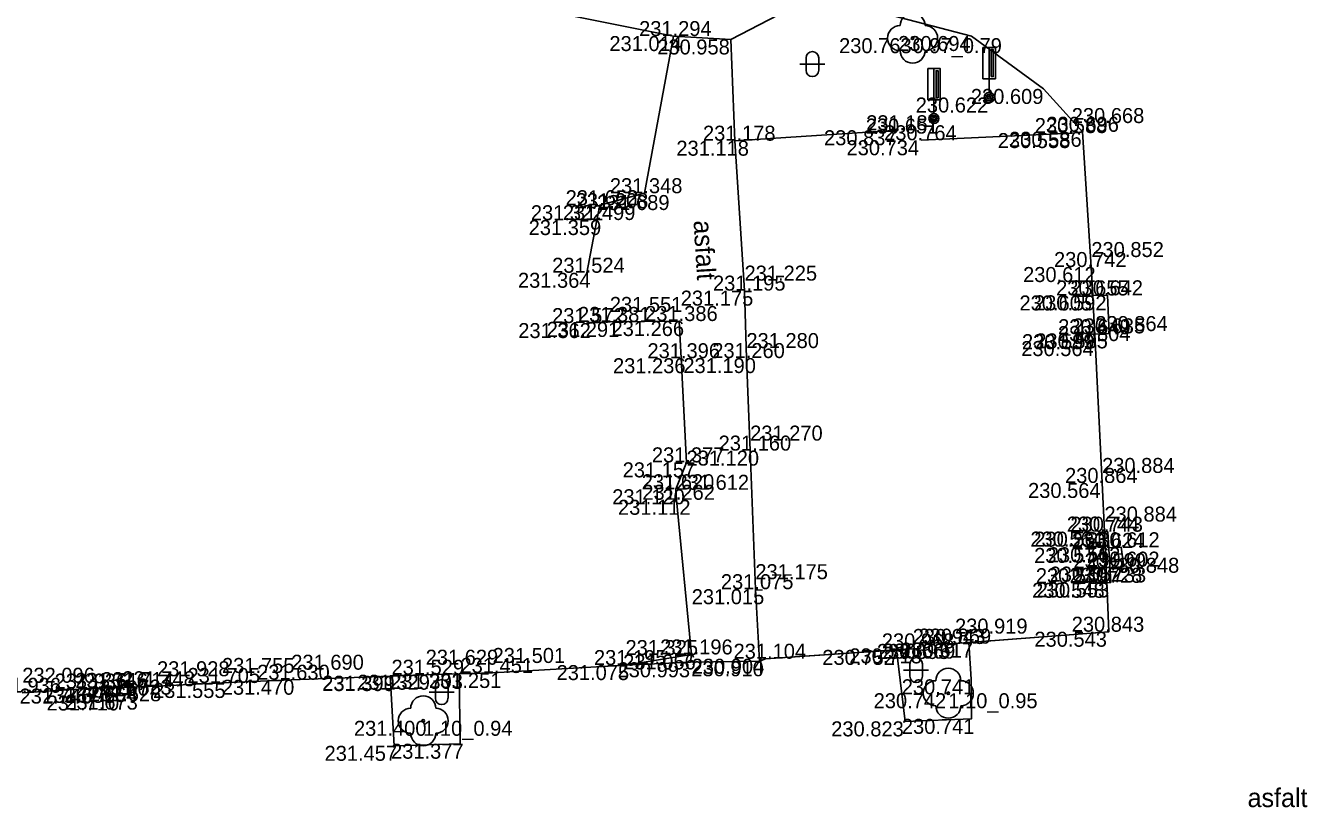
# Model space of a CAD drawing. Extents: x -599516 to -599132, y -1163668 to -1163119.
# Drawn here: x -599461.53 to -599435.91, y -1163173.88 to -1163158.24 of the extents above; entities that cross this region are included whole.
import ezdxf

# ---------------------------------------------------------------- set-up
doc = ezdxf.new("R2010")
doc.units = 0
for name, color, linetype in [('Bod-oznac1', 7, 'Continuous'), ('Bod-oznac2', 7, 'Continuous'), ('Bod-oznac3', 7, 'Continuous'), ('Bod-vyska1', 7, 'Continuous'), ('Bod-vyska2', 7, 'Continuous'), ('Bod-vyska3', 7, 'Continuous'), ('Z_cela-hrobu-dolni-linie', 7, 'Continuous'), ('Z_cela-hrobu-horni-linie', 7, 'Continuous'), ('Z_chodnik', 7, 'Continuous'), ('Z_komunikace', 7, 'Continuous'), ('Z_kultury-znacky', 7, 'Continuous'), ('Z_obvod-kmene-spodek-ve-vysce1_2m', 7, 'Continuous'), ('Z_popis-budov-povrchu', 7, 'Continuous'), ('Z_stromy-kere', 7, 'Continuous'), ('Z_znacky-ostatni-orientacni-sloupek', 7, 'Continuous'), ('Z_zpevnene-plochy', 7, 'Continuous')]:
    doc.layers.add(name, color=color, linetype=linetype)

msp = doc.modelspace()

# ---------------------------------------------------------------- linework, layer by layer
at = {"layer": 'Bod-oznac1'}
for p, q in [((-599448.581, -1163158.452), (-599448.581, -1163158.452)), ((-599443.802, -1163158.494), (-599443.802, -1163158.494)), ((-599442.623, -1163158.451), (-599442.623, -1163158.451)), ((-599447.439, -1163158.52), (-599447.439, -1163158.52)), ((-599441.182, -1163159.51), (-599441.182, -1163159.51)), ((-599442.272, -1163159.681), (-599442.272, -1163159.681)), ((-599443.375, -1163160.103), (-599443.375, -1163160.103)), ((-599447.355, -1163160.545), (-599447.355, -1163160.545)), ((-599444.092, -1163160.336), (-599444.092, -1163160.336)), ((-599443.63, -1163160.536), (-599443.63, -1163160.536)), ((-599440.62, -1163160.392), (-599440.62, -1163160.392)), ((-599440.405, -1163160.367), (-599440.405, -1163160.367)), ((-599450.056, -1163161.836), (-599450.056, -1163161.836)), ((-599449.16, -1163161.595), (-599449.16, -1163161.595)), ((-599450.112, -1163162.132), (-599450.112, -1163162.132)), ((-599440.229, -1163163.072), (-599440.229, -1163163.072)), ((-599450.314, -1163163.187), (-599450.314, -1163163.187)), ((-599447.162, -1163163.544), (-599447.162, -1163163.544)), ((-599439.907, -1163163.638), (-599439.907, -1163163.638)), ((-599440.199, -1163163.641), (-599440.199, -1163163.641)), ((-599448.466, -1163164.152), (-599448.466, -1163164.152)), ((-599450.32, -1163164.193), (-599450.32, -1163164.193)), ((-599449.855, -1163164.17), (-599449.855, -1163164.17)), ((-599439.87, -1163164.399), (-599439.87, -1163164.399)), ((-599440.158, -1163164.415), (-599440.158, -1163164.415)), ((-599440.151, -1163164.553), (-599440.151, -1163164.553)), ((-599448.426, -1163164.896), (-599448.426, -1163164.896)), ((-599447.125, -1163164.893), (-599447.125, -1163164.893)), ((-599447.05, -1163166.744), (-599447.05, -1163166.744)), ((-599448.323, -1163166.979), (-599448.323, -1163166.979)), ((-599440.014, -1163167.391), (-599440.014, -1163167.391)), ((-599448.535, -1163167.517), (-599448.535, -1163167.517)), ((-599448.522, -1163167.728), (-599448.522, -1163167.728)), ((-599439.967, -1163168.364), (-599439.967, -1163168.364)), ((-599439.901, -1163168.366), (-599439.901, -1163168.366)), ((-599439.879, -1163168.691), (-599439.879, -1163168.691)), ((-599439.631, -1163168.678), (-599439.631, -1163168.678)), ((-599439.858, -1163169.096), (-599439.858, -1163169.096)), ((-599439.582, -1163169.065), (-599439.582, -1163169.065)), ((-599446.946, -1163169.516), (-599446.946, -1163169.516)), ((-599439.921, -1163169.388), (-599439.921, -1163169.388)), ((-599439.842, -1163169.381), (-599439.842, -1163169.381)), ((-599439.876, -1163170.367), (-599439.876, -1163170.367)), ((-599444.126, -1163170.73), (-599444.126, -1163170.73)), ((-599443.689, -1163170.7), (-599443.689, -1163170.7)), ((-599443.059, -1163170.612), (-599443.059, -1163170.612)), ((-599442.954, -1163170.605), (-599442.954, -1163170.605)), ((-599442.678, -1163170.584), (-599442.678, -1163170.584)), ((-599449.542, -1163171.034), (-599449.542, -1163171.034)), ((-599448.244, -1163170.978), (-599448.244, -1163170.978)), ((-599448.224, -1163170.821), (-599448.224, -1163170.821)), ((-599446.865, -1163170.958), (-599446.865, -1163170.958)), ((-599446.74, -1163170.907), (-599446.74, -1163170.907)), ((-599456.224, -1163171.327), (-599456.224, -1163171.327)), ((-599454.25, -1163171.247), (-599454.25, -1163171.247)), ((-599454.25, -1163171.254), (-599454.25, -1163171.254)), ((-599453.537, -1163171.227), (-599453.537, -1163171.227)), ((-599452.868, -1163171.21), (-599452.868, -1163171.21)), ((-599452.199, -1163171.192), (-599452.199, -1163171.192)), ((-599442.63, -1163171.319), (-599442.63, -1163171.319)), ((-599460.278, -1163171.504), (-599460.278, -1163171.504)), ((-599459.853, -1163171.491), (-599459.853, -1163171.491)), ((-599459.384, -1163171.475), (-599459.384, -1163171.475)), ((-599458.908, -1163171.458), (-599458.908, -1163171.458)), ((-599457.61, -1163171.392), (-599457.61, -1163171.392)), ((-599459.842, -1163171.642), (-599459.842, -1163171.642)), ((-599459.375, -1163171.625), (-599459.375, -1163171.625)), ((-599443.088, -1163171.597), (-599443.088, -1163171.597)), ((-599453.586, -1163172.149), (-599453.586, -1163172.149)), ((-599443.949, -1163172.16), (-599443.949, -1163172.16)), ((-599442.627, -1163172.11), (-599442.627, -1163172.11)), ((-599452.848, -1163172.607), (-599452.848, -1163172.607)), ((-599454.168, -1163172.649), (-599454.168, -1163172.649))]:
    msp.add_line(p, q, dxfattribs=at)
at = {"layer": 'Bod-oznac2'}
for p, q in [((-599448.581, -1163158.452), (-599448.581, -1163158.452)), ((-599447.355, -1163160.545), (-599447.355, -1163160.545)), ((-599444.092, -1163160.336), (-599444.092, -1163160.336)), ((-599443.63, -1163160.536), (-599443.63, -1163160.536)), ((-599440.62, -1163160.392), (-599440.62, -1163160.392)), ((-599440.405, -1163160.367), (-599440.405, -1163160.367)), ((-599450.056, -1163161.836), (-599450.056, -1163161.836)), ((-599449.16, -1163161.595), (-599449.16, -1163161.595)), ((-599450.112, -1163162.132), (-599450.112, -1163162.132)), ((-599440.229, -1163163.072), (-599440.229, -1163163.072)), ((-599450.314, -1163163.187), (-599450.314, -1163163.187)), ((-599447.162, -1163163.544), (-599447.162, -1163163.544)), ((-599439.907, -1163163.638), (-599439.907, -1163163.638)), ((-599440.199, -1163163.641), (-599440.199, -1163163.641)), ((-599448.466, -1163164.152), (-599448.466, -1163164.152)), ((-599450.32, -1163164.193), (-599450.32, -1163164.193)), ((-599449.855, -1163164.17), (-599449.855, -1163164.17)), ((-599439.87, -1163164.399), (-599439.87, -1163164.399)), ((-599440.158, -1163164.415), (-599440.158, -1163164.415)), ((-599440.151, -1163164.553), (-599440.151, -1163164.553)), ((-599448.426, -1163164.896), (-599448.426, -1163164.896)), ((-599447.125, -1163164.893), (-599447.125, -1163164.893)), ((-599447.05, -1163166.744), (-599447.05, -1163166.744)), ((-599448.323, -1163166.979), (-599448.323, -1163166.979)), ((-599440.014, -1163167.391), (-599440.014, -1163167.391)), ((-599448.535, -1163167.517), (-599448.535, -1163167.517)), ((-599448.522, -1163167.728), (-599448.522, -1163167.728)), ((-599439.967, -1163168.364), (-599439.967, -1163168.364)), ((-599439.901, -1163168.366), (-599439.901, -1163168.366)), ((-599439.879, -1163168.691), (-599439.879, -1163168.691)), ((-599439.631, -1163168.678), (-599439.631, -1163168.678)), ((-599439.858, -1163169.096), (-599439.858, -1163169.096)), ((-599439.582, -1163169.065), (-599439.582, -1163169.065)), ((-599446.946, -1163169.516), (-599446.946, -1163169.516)), ((-599439.921, -1163169.388), (-599439.921, -1163169.388)), ((-599439.842, -1163169.381), (-599439.842, -1163169.381)), ((-599439.876, -1163170.367), (-599439.876, -1163170.367)), ((-599443.689, -1163170.7), (-599443.689, -1163170.7)), ((-599443.059, -1163170.612), (-599443.059, -1163170.612)), ((-599442.954, -1163170.605), (-599442.954, -1163170.605)), ((-599449.542, -1163171.034), (-599449.542, -1163171.034)), ((-599448.224, -1163170.821), (-599448.224, -1163170.821)), ((-599446.74, -1163170.907), (-599446.74, -1163170.907)), ((-599456.224, -1163171.327), (-599456.224, -1163171.327)), ((-599453.537, -1163171.227), (-599453.537, -1163171.227)), ((-599452.199, -1163171.192), (-599452.199, -1163171.192)), ((-599460.278, -1163171.504), (-599460.278, -1163171.504)), ((-599459.853, -1163171.491), (-599459.853, -1163171.491)), ((-599459.384, -1163171.475), (-599459.384, -1163171.475)), ((-599458.908, -1163171.458), (-599458.908, -1163171.458)), ((-599457.61, -1163171.392), (-599457.61, -1163171.392)), ((-599459.842, -1163171.642), (-599459.842, -1163171.642)), ((-599459.375, -1163171.625), (-599459.375, -1163171.625))]:
    msp.add_line(p, q, dxfattribs=at)
at = {"layer": 'Bod-oznac3'}
for p, q in [((-599440.62, -1163160.392), (-599440.62, -1163160.392)), ((-599450.112, -1163162.132), (-599450.112, -1163162.132)), ((-599440.229, -1163163.072), (-599440.229, -1163163.072)), ((-599447.162, -1163163.544), (-599447.162, -1163163.544)), ((-599449.855, -1163164.17), (-599449.855, -1163164.17)), ((-599440.151, -1163164.553), (-599440.151, -1163164.553)), ((-599447.125, -1163164.893), (-599447.125, -1163164.893)), ((-599447.05, -1163166.744), (-599447.05, -1163166.744)), ((-599440.014, -1163167.391), (-599440.014, -1163167.391)), ((-599448.522, -1163167.728), (-599448.522, -1163167.728)), ((-599439.967, -1163168.364), (-599439.967, -1163168.364)), ((-599446.946, -1163169.516), (-599446.946, -1163169.516)), ((-599439.921, -1163169.388), (-599439.921, -1163169.388)), ((-599442.954, -1163170.605), (-599442.954, -1163170.605)), ((-599449.542, -1163171.034), (-599449.542, -1163171.034)), ((-599456.224, -1163171.327), (-599456.224, -1163171.327)), ((-599453.537, -1163171.227), (-599453.537, -1163171.227)), ((-599452.199, -1163171.192), (-599452.199, -1163171.192)), ((-599458.908, -1163171.458), (-599458.908, -1163171.458)), ((-599457.61, -1163171.392), (-599457.61, -1163171.392))]:
    msp.add_line(p, q, dxfattribs=at)
at = {"layer": 'Z_cela-hrobu-dolni-linie'}
for p, q in [((-599447.355, -1163160.545), (-599444.092, -1163160.336)), ((-599439.921, -1163169.388), (-599439.967, -1163168.364)), ((-599444.126, -1163170.73), (-599443.689, -1163170.7)), ((-599449.542, -1163171.034), (-599448.224, -1163170.821)), ((-599453.537, -1163171.227), (-599454.25, -1163171.247)), ((-599453.537, -1163171.227), (-599452.868, -1163171.21))]:
    msp.add_line(p, q, dxfattribs=at)
for points in [[(-599443.63, -1163160.536), (-599440.62, -1163160.392), (-599440.405, -1163160.367)], [(-599443.059, -1163170.612), (-599442.954, -1163170.605), (-599442.678, -1163170.584)]]:
    msp.add_lwpolyline(points, dxfattribs=at)
at = {"layer": 'Z_cela-hrobu-horni-linie'}
for p, q in [((-599449.16, -1163161.595), (-599448.581, -1163158.452)), ((-599443.689, -1163170.7), (-599446.74, -1163170.907))]:
    msp.add_line(p, q, dxfattribs=at)
for points in [[(-599462.314, -1163155.831), (-599460.821, -1163156.098), (-599460.821, -1163156.098), (-599459.48, -1163156.355), (-599459.48, -1163156.355), (-599456.681, -1163156.866), (-599456.681, -1163156.866), (-599455.323, -1163157.146), (-599455.323, -1163157.146), (-599453.959, -1163157.398), (-599453.959, -1163157.398), (-599452.55, -1163157.668), (-599452.55, -1163157.668), (-599451.218, -1163157.928), (-599451.218, -1163157.928), (-599448.581, -1163158.452)], [(-599444.092, -1163160.336), (-599447.355, -1163160.545), (-599447.162, -1163163.544), (-599447.162, -1163163.544), (-599447.125, -1163164.893), (-599447.125, -1163164.893), (-599447.05, -1163166.744), (-599447.05, -1163166.744), (-599446.946, -1163169.516), (-599446.946, -1163169.516)], [(-599443.63, -1163160.536), (-599440.62, -1163160.392), (-599440.62, -1163160.392), (-599440.405, -1163160.367), (-599440.229, -1163163.072), (-599440.229, -1163163.072), (-599440.151, -1163164.553), (-599440.151, -1163164.553), (-599440.014, -1163167.391), (-599440.014, -1163167.391), (-599439.967, -1163168.364), (-599439.921, -1163169.388), (-599439.876, -1163170.367), (-599442.954, -1163170.605), (-599442.954, -1163170.605), (-599443.059, -1163170.612)], [(-599450.056, -1163161.836), (-599450.112, -1163162.132), (-599450.112, -1163162.132), (-599450.314, -1163163.187)], [(-599450.32, -1163164.193), (-599449.855, -1163164.17), (-599449.855, -1163164.17), (-599448.466, -1163164.152), (-599448.426, -1163164.896), (-599448.323, -1163166.979)], [(-599448.535, -1163167.517), (-599448.522, -1163167.728), (-599448.522, -1163167.728), (-599448.224, -1163170.821), (-599449.542, -1163171.034), (-599449.542, -1163171.034), (-599452.199, -1163171.192), (-599452.199, -1163171.192), (-599453.537, -1163171.227), (-599453.537, -1163171.227), (-599456.224, -1163171.327), (-599456.224, -1163171.327), (-599457.61, -1163171.392), (-599457.61, -1163171.392), (-599458.908, -1163171.458), (-599458.908, -1163171.458), (-599460.278, -1163171.504), (-599461.602, -1163171.588)]]:
    msp.add_lwpolyline(points, dxfattribs=at)
at = {"layer": 'Z_chodnik'}
for points in [[(-599448.581, -1163158.452), (-599449.16, -1163161.595), (-599450.056, -1163161.836), (-599450.112, -1163162.132), (-599450.314, -1163163.187)], [(-599447.125, -1163164.893), (-599447.162, -1163163.544), (-599447.355, -1163160.545), (-599447.439, -1163158.52)], [(-599450.32, -1163164.193), (-599449.855, -1163164.17), (-599448.466, -1163164.152), (-599448.426, -1163164.896)], [(-599448.426, -1163164.896), (-599448.323, -1163166.979), (-599448.535, -1163167.517)], [(-599446.865, -1163170.958), (-599446.946, -1163169.516), (-599447.05, -1163166.744), (-599447.125, -1163164.893)], [(-599448.535, -1163167.517), (-599448.522, -1163167.728), (-599448.224, -1163170.821), (-599448.244, -1163170.978)]]:
    msp.add_lwpolyline(points, dxfattribs=at)
at = {"layer": 'Z_komunikace'}
msp.add_line((-599441.182, -1163159.51), (-599440.405, -1163160.367), dxfattribs=at)
for points in [[(-599451.218, -1163157.928), (-599448.581, -1163158.452), (-599447.439, -1163158.52), (-599446.11, -1163157.833)], [(-599445.006, -1163157.835), (-599442.623, -1163158.451), (-599441.182, -1163159.51)], [(-599440.405, -1163160.367), (-599440.229, -1163163.072), (-599440.199, -1163163.641), (-599439.907, -1163163.638), (-599439.87, -1163164.399), (-599440.158, -1163164.415), (-599440.151, -1163164.553), (-599440.014, -1163167.391), (-599439.967, -1163168.364), (-599439.901, -1163168.366), (-599439.879, -1163168.691), (-599439.631, -1163168.678), (-599439.582, -1163169.065), (-599439.858, -1163169.096), (-599439.842, -1163169.381), (-599439.921, -1163169.388), (-599439.876, -1163170.367), (-599442.678, -1163170.584), (-599442.63, -1163171.319), (-599442.627, -1163172.11), (-599443.949, -1163172.16), (-599444.126, -1163170.73), (-599446.74, -1163170.907), (-599446.865, -1163170.958), (-599448.244, -1163170.978), (-599449.542, -1163171.034), (-599452.199, -1163171.192), (-599452.868, -1163171.21), (-599452.848, -1163172.607), (-599454.168, -1163172.649), (-599454.25, -1163171.254), (-599456.224, -1163171.327), (-599457.61, -1163171.392), (-599458.908, -1163171.458), (-599459.384, -1163171.475), (-599459.375, -1163171.625), (-599459.842, -1163171.642), (-599459.853, -1163171.491), (-599460.278, -1163171.504), (-599461.602, -1163171.588)]]:
    msp.add_lwpolyline(points, dxfattribs=at)
at = {"layer": 'Z_kultury-znacky'}
for p, q in [((-599446.055, -1163159.012), (-599445.555, -1163159.012)), ((-599445.93, -1163158.887), (-599445.93, -1163159.137)), ((-599445.68, -1163158.887), (-599445.68, -1163159.137)), ((-599443.857, -1163171.008), (-599443.857, -1163171.258)), ((-599443.607, -1163171.008), (-599443.607, -1163171.258)), ((-599443.982, -1163171.133), (-599443.482, -1163171.133)), ((-599453.465, -1163171.573), (-599452.965, -1163171.573)), ((-599453.34, -1163171.448), (-599453.34, -1163171.698)), ((-599453.09, -1163171.448), (-599453.09, -1163171.698))]:
    msp.add_line(p, q, dxfattribs=at)
for centre, start, end in [((-599445.805, -1163158.887), 0, 180), ((-599445.805, -1163159.137), 180, 0), ((-599443.732, -1163171.008), 0, 180), ((-599453.216, -1163171.448), 0, 180), ((-599443.732, -1163171.258), 180, 0), ((-599453.216, -1163171.698), 180, 0)]:
    msp.add_arc(centre, 0.125, start, end, dxfattribs=at)
at = {"layer": 'Z_stromy-kere'}
for centre in [(-599443.802, -1163158.494), (-599443.088, -1163171.597), (-599453.586, -1163172.149)]:
    msp.add_circle(centre, 0.025, dxfattribs=at)
for centre, start, end in [((-599443.802, -1163158.244), 0, 180), ((-599444.052, -1163158.494), 90, 270), ((-599443.552, -1163158.494), 270, 90), ((-599443.802, -1163158.744), 180, 0), ((-599443.088, -1163171.347), 0, 180), ((-599443.338, -1163171.597), 90, 270), ((-599442.838, -1163171.597), 270, 90), ((-599453.586, -1163171.899), 0, 180), ((-599453.836, -1163172.149), 90, 270), ((-599453.336, -1163172.149), 270, 90), ((-599443.088, -1163171.847), 180, 0), ((-599453.586, -1163172.399), 180, 0)]:
    msp.add_arc(centre, 0.25, start, end, dxfattribs=at)
at = {"layer": 'Z_znacky-ostatni-orientacni-sloupek'}
for p, q in [((-599442.397, -1163158.681), (-599442.397, -1163159.306)), ((-599442.397, -1163158.681), (-599442.272, -1163158.681)), ((-599443.5, -1163159.103), (-599443.5, -1163159.728)), ((-599443.5, -1163159.103), (-599443.375, -1163159.103)), ((-599442.397, -1163159.306), (-599442.272, -1163159.306)), ((-599442.272, -1163159.306), (-599442.272, -1163159.581)), ((-599443.5, -1163159.728), (-599443.375, -1163159.728)), ((-599443.375, -1163159.728), (-599443.375, -1163160.003))]:
    msp.add_line(p, q, dxfattribs=at)
for points in [[(-599442.272, -1163159.306), (-599442.147, -1163159.306), (-599442.147, -1163158.681), (-599442.272, -1163158.681)], [(-599442.23, -1163159.264), (-599442.189, -1163159.264), (-599442.189, -1163158.724), (-599442.23, -1163158.724)], [(-599443.375, -1163159.728), (-599443.25, -1163159.728), (-599443.25, -1163159.103), (-599443.375, -1163159.103)], [(-599443.333, -1163159.686), (-599443.292, -1163159.686), (-599443.292, -1163159.146), (-599443.333, -1163159.146)]]:
    msp.add_lwpolyline(points, close=True, dxfattribs=at)
for centre, radius in [((-599442.272, -1163159.681), 0.1), ((-599442.272, -1163159.681), 0.065), ((-599442.272, -1163159.681), 0.03), ((-599443.375, -1163160.103), 0.1), ((-599443.375, -1163160.103), 0.065), ((-599443.375, -1163160.103), 0.03)]:
    msp.add_circle(centre, radius, dxfattribs=at)
at = {"layer": 'Z_zpevnene-plochy'}
for points in [[(-599440.158, -1163164.415), (-599439.87, -1163164.399), (-599439.907, -1163163.638), (-599440.199, -1163163.641)], [(-599439.921, -1163169.388), (-599439.842, -1163169.381), (-599439.901, -1163168.366), (-599439.967, -1163168.364)], [(-599439.858, -1163169.096), (-599439.582, -1163169.065), (-599439.631, -1163168.678), (-599439.879, -1163168.691)], [(-599459.853, -1163171.491), (-599459.842, -1163171.642), (-599459.375, -1163171.625), (-599459.384, -1163171.475)]]:
    msp.add_lwpolyline(points, dxfattribs=at)

# ---------------------------------------------------------------- texts
at = {"layer": 'Bod-vyska1'}
for s, p in [('231.014', (-599449.864, -1163158.752)), ('230.763', (-599445.272, -1163158.794)), ('230.694', (-599444.091, -1163158.751)), ('230.958', (-599448.907, -1163158.82)), ('230.609', (-599442.637, -1163159.81)), ('230.622', (-599443.74, -1163159.981)), ('230.651', (-599444.739, -1163160.403)), ('231.118', (-599448.525, -1163160.845)), ('230.837', (-599445.573, -1163160.636)), ('230.734', (-599445.123, -1163160.836)), ('230.558', (-599442.1, -1163160.692)), ('230.586', (-599441.873, -1163160.667)), ('231.322', (-599451.434, -1163162.136)), ('231.208', (-599450.536, -1163161.895)), ('231.359', (-599451.478, -1163162.432)), ('230.612', (-599441.593, -1163163.372)), ('231.364', (-599451.692, -1163163.487)), ('231.175', (-599448.437, -1163163.844)), ('230.605', (-599441.665, -1163163.941)), ('230.592', (-599441.375, -1163163.938)), ('231.266', (-599449.821, -1163164.452)), ('231.362', (-599451.686, -1163164.493)), ('231.291', (-599451.117, -1163164.47)), ('230.585', (-599441.35, -1163164.699)), ('230.564', (-599441.631, -1163164.853)), ('230.599', (-599441.615, -1163164.715)), ('231.236', (-599449.792, -1163165.196)), ('231.190', (-599448.385, -1163165.193)), ('231.120', (-599448.322, -1163167.044)), ('231.157', (-599449.599, -1163167.279)), ('230.564', (-599441.494, -1163167.691)), ('231.120', (-599449.807, -1163167.817)), ('231.112', (-599449.692, -1163168.028)), ('230.564', (-599441.447, -1163168.664)), ('230.563', (-599441.369, -1163168.666)), ('230.574', (-599441.372, -1163168.991)), ('230.562', (-599441.099, -1163168.978)), ('230.549', (-599441.338, -1163169.396)), ('230.552', (-599441.062, -1163169.365)), ('231.015', (-599448.218, -1163169.816)), ('230.548', (-599441.412, -1163169.688)), ('230.553', (-599441.322, -1163169.681)), ('230.543', (-599441.367, -1163170.667)), ('230.752', (-599445.607, -1163171.03)), ('230.718', (-599445.067, -1163171)), ('230.693', (-599444.516, -1163170.912)), ('230.669', (-599444.4, -1163170.905)), ('230.617', (-599444.044, -1163170.884)), ('231.075', (-599450.92, -1163171.334)), ('230.993', (-599449.701, -1163171.278)), ('231.056', (-599449.588, -1163171.121)), ('230.910', (-599448.227, -1163171.258)), ('230.904', (-599448.218, -1163171.207)), ('231.470', (-599457.613, -1163171.627)), ('231.399', (-599455.605, -1163171.547)), ('231.399', (-599455.605, -1163171.554)), ('231.329', (-599454.903, -1163171.527)), ('231.303', (-599454.244, -1163171.51)), ('231.251', (-599453.473, -1163171.492)), ('230.741', (-599444.019, -1163171.619)), ('231.746', (-599461.657, -1163171.804)), ('231.696', (-599461.197, -1163171.791)), ('231.664', (-599460.75, -1163171.775)), ('231.628', (-599460.274, -1163171.758)), ('231.555', (-599458.988, -1163171.692)), ('231.710', (-599461.116, -1163171.942)), ('231.673', (-599460.743, -1163171.925)), ('230.742', (-599444.581, -1163171.897)), ('231.400', (-599454.971, -1163172.449)), ('230.823', (-599445.429, -1163172.46)), ('230.741', (-599444.016, -1163172.41)), ('231.377', (-599454.229, -1163172.907)), ('231.457', (-599455.559, -1163172.949))]:
    msp.add_text(s, height=0.3, dxfattribs=at).set_placement(p)
at = {"layer": 'Bod-vyska2'}
for s, p in [('231.294', (-599449.27, -1163158.452)), ('231.187', (-599444.73, -1163160.336)), ('231.178', (-599447.993, -1163160.545)), ('230.764', (-599444.371, -1163160.536)), ('230.588', (-599441.36, -1163160.392)), ('230.696', (-599441.128, -1163160.367)), ('231.348', (-599449.854, -1163161.595)), ('231.652', (-599450.739, -1163161.836)), ('231.499', (-599450.795, -1163162.132)), ('230.742', (-599440.975, -1163163.072)), ('231.524', (-599451.008, -1163163.187)), ('231.195', (-599447.793, -1163163.544)), ('230.655', (-599440.933, -1163163.641)), ('230.642', (-599440.647, -1163163.638)), ('231.572', (-599451.01, -1163164.193)), ('231.381', (-599450.492, -1163164.17)), ('231.386', (-599449.149, -1163164.152)), ('230.649', (-599440.892, -1163164.415)), ('230.635', (-599440.604, -1163164.399)), ('230.804', (-599440.896, -1163164.553)), ('231.396', (-599449.103, -1163164.896)), ('231.260', (-599447.807, -1163164.893)), ('231.160', (-599447.68, -1163166.744)), ('231.377', (-599449.014, -1163166.979)), ('231.620', (-599449.217, -1163167.517)), ('230.864', (-599440.754, -1163167.391)), ('231.262', (-599449.205, -1163167.728)), ('230.744', (-599440.719, -1163168.364)), ('230.743', (-599440.647, -1163168.366)), ('230.624', (-599440.619, -1163168.691)), ('230.612', (-599440.313, -1163168.678)), ('230.602', (-599440.315, -1163169.065)), ('230.599', (-599440.586, -1163169.096)), ('231.075', (-599447.635, -1163169.516)), ('230.728', (-599440.662, -1163169.388)), ('230.733', (-599440.583, -1163169.381)), ('230.869', (-599443.682, -1163170.605)), ('230.843', (-599440.621, -1163170.367)), ('231.196', (-599448.849, -1163170.821)), ('230.968', (-599444.417, -1163170.7)), ('230.943', (-599443.799, -1163170.612)), ('231.195', (-599450.173, -1163171.034)), ('231.104', (-599447.382, -1163170.907)), ('231.630', (-599456.906, -1163171.327)), ('231.529', (-599454.22, -1163171.227)), ('231.451', (-599452.841, -1163171.192)), ('231.936', (-599462.279, -1163171.588)), ('231.936', (-599460.955, -1163171.504)), ('231.746', (-599460.543, -1163171.491)), ('231.723', (-599460.065, -1163171.625)), ('231.714', (-599460.027, -1163171.475)), ('231.748', (-599459.603, -1163171.458)), ('231.705', (-599458.299, -1163171.392)), ('231.760', (-599460.525, -1163171.642))]:
    msp.add_text(s, height=0.3, dxfattribs=at).set_placement(p)
at = {"layer": 'Bod-vyska3'}
for s, p in [('230.668', (-599440.62, -1163160.192)), ('231.689', (-599450.112, -1163161.932)), ('230.852', (-599440.229, -1163162.872)), ('231.225', (-599447.162, -1163163.344)), ('231.551', (-599449.855, -1163163.97)), ('230.864', (-599440.151, -1163164.353)), ('231.280', (-599447.125, -1163164.693)), ('231.270', (-599447.05, -1163166.544)), ('230.884', (-599440.014, -1163167.191)), ('231.612', (-599448.522, -1163167.528)), ('230.884', (-599439.967, -1163168.164)), ('231.175', (-599446.946, -1163169.316)), ('230.848', (-599439.921, -1163169.188)), ('230.919', (-599442.954, -1163170.405)), ('231.325', (-599449.542, -1163170.834)), ('231.629', (-599453.537, -1163171.027)), ('231.501', (-599452.199, -1163170.992)), ('231.928', (-599458.908, -1163171.258)), ('231.755', (-599457.61, -1163171.192)), ('231.690', (-599456.224, -1163171.127)), ('232.096', (-599461.602, -1163171.388))]:
    msp.add_text(s, height=0.3, dxfattribs=at).set_placement(p)
at = {"layer": 'Z_obvod-kmene-spodek-ve-vysce1_2m'}
for s, p in [('0.97_0.79', (-599443.802, -1163158.794)), ('1.10_0.95', (-599443.088, -1163171.897)), ('1.10_0.94', (-599453.586, -1163172.449))]:
    msp.add_text(s, height=0.3, dxfattribs=at).set_placement(p)
at = {"layer": 'Z_popis-budov-povrchu'}
msp.add_text('asfalt', height=0.375, rotation=273.4503, dxfattribs=at).set_placement((-599448.182, -1163162.147))
msp.add_text('asfalt', height=0.375, dxfattribs=at).set_placement((-599437.105, -1163173.875))

doc.saveas('drawing.dxf')
